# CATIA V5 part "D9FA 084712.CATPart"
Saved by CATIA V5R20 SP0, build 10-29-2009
Part number: D9FA 084712
Revision: ANY
Definition: UNKNOWN
Nomenclature: D9FA 084712
Source: Unknown
Bounding box of the stored display mesh (mm): x -4 to 3.804, y -10 to 10, z -4 to 4
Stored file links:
  C:\Users\Utente\Desktop\IO LAVORO\3D X SITO CF\CUMSA\3D files FA\FA 084712-21\D9FA 084712.CATPart

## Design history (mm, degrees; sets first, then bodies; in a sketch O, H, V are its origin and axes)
Body1 "Cortar-Extruir5" (main body)
  Solid1: solid without history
